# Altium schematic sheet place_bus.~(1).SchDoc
size A4
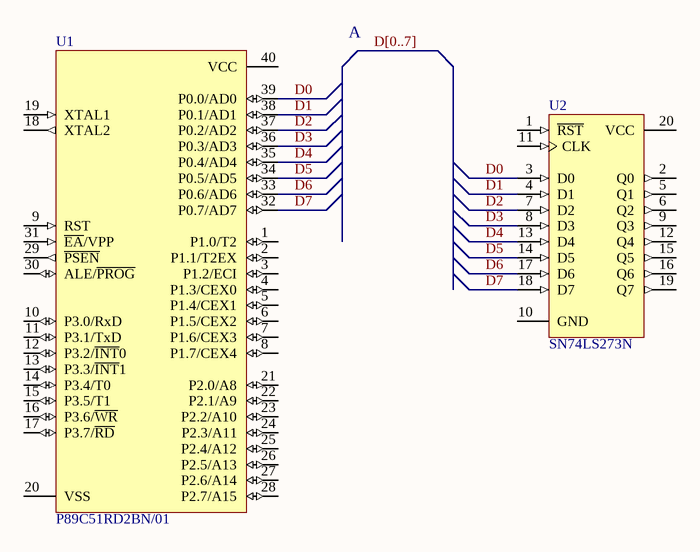
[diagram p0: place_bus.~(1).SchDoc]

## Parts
U1  P89C51RD2BN/01  [SOT129-1]
U2  SN74LS273N  [N020]

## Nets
D0: U1.39(P0.0/AD0) U2.3(D0)
D1: U1.38(P0.1/AD1) U2.4(D1)
D2: U1.37(P0.2/AD2) U2.7(D2)
D3: U1.36(P0.3/AD3) U2.8(D3)
D4: U1.35(P0.4/AD4) U2.13(D4)
D5: U1.34(P0.5/AD5) U2.14(D5)
D6: U1.33(P0.6/AD6) U2.17(D6)
D7: U1.32(P0.7/AD7) U2.18(D7)

Not connected (* = marked no-connect by the designer): U1 1(P1.0/T2) 2(P1.1/T2EX) 3(P1.2/ECI) 4(P1.3/CEX0) 5(P1.4/CEX1) 6(P1.5/CEX2) 7(P1.6/CEX3) 8(P1.7/CEX4) 9(RST) 10(P3.0/RxD) 11(P3.1/TxD) 12(P3.2/~{INT}0) 13(P3.3/~{INT}1) 14(P3.4/T0) 15(P3.5/T1) 16(P3.6/~{WR}) 17(P3.7/~{RD}) 18(XTAL2) 19(XTAL1) 20(VSS) 21(P2.0/A8) 22(P2.1/A9) 23(P2.2/A10) 24(P2.3/A11) 25(P2.4/A12) 26(P2.5/A13) 27(P2.6/A14) 28(P2.7/A15) 29(~{PSEN}) 30(ALE/~{PROG}) 31(~{EA}/VPP) 40(VCC); U2 1(~{RST}) 2(Q0) 5(Q1) 6(Q2) 9(Q3) 10(GND) 11(CLK) 12(Q4) 15(Q5) 16(Q6) 19(Q7) 20(VCC)

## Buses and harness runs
bus D[0..7]

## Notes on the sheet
- A

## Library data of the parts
U1 = P89C51RD2BN/01: 80C51 8-Bit Flash Microcontroller Family, 64 kB ISP/IAP Flash with 1 kB RAM.
U2 = SN74LS273N: Octal D-Type Flip-Flop with Clear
